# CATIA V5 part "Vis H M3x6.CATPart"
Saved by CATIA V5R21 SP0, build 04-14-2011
Part number: Vis H M3x6
Material "Acier": density 7860 kg/m3, Young's modulus 2e+11 Pa, Poisson ratio 0.266, thermal expansion 1.17e-05 1/K
Bounding box of the stored display mesh (mm): x -2.5 to 2.5, y -2.887 to 2.887, z 0 to 8
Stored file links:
  C:\Users\Olivier\Desktop\redaction CATIA (local)\CATIA\DONNEES\Exercice assemblage 1 (chassis et socle)\Assemblage chassis et socle (Product inclus)\Vis H M3x6.CATPart
  C:\Program Files\Dassault Systemes\B21\win_b64\startup\materials\French\Catalog.CATMaterial
  C:\Users\Olivier\Desktop\redaction CATIA (local)\CATIA\DONNEES\Exercice assemblage 1 (chassis et socle)\Assemblage chassis et socle (Product inclus)\CATIA_EnvironmentMap_Satin_512x512.jpg
  C:\Users\Olivier\Desktop\redaction CATIA (local)\pompe à moteur de ventilation refait\Pompe_a_moteur_de_ventilation.CATProduct
  C:\Users\Olivier\Desktop\redaction CATIA (local)\pompe à moteur de ventilation refait\Ecrou a collerette M5.CATPart
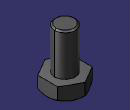
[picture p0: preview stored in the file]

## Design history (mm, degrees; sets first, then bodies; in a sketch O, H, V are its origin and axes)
Body1 (main body), material "Acier"
  Sketch1 on xy-plane, origin (0, 0, 0), H (1, 0, 0), V (0, 1, 0)
    circle A1 centre (0, 0) radius 1.5
    point P1 (2.5, -1.4434)
    point P2 (2.5, 1.4434)
    point P3 (0, 2.8868)
    point P4 (-2.5, 1.4434)
    point P5 (-2.5, -1.4434)
    point P6 (0, -2.8868)
    point P7 (2.5, 0)
    line L1 (2.5, -1.4434) -> (2.5, 1.4434)
    line L2 (2.5, 1.4434) -> (0, 2.8868)
    line L3 (0, 2.8868) -> (-2.5, 1.4434)
    line L4 (-2.5, 1.4434) -> (-2.5, -1.4434)
    line L5 (-2.5, -1.4434) -> (0, -2.8868)
    line L6 (0, -2.8868) -> (2.5, -1.4434)
    construction line L7 (0, 0) -> (2.5, 0)
    construction circle A2 centre (0, 0) radius 2.8868
    construction arc A3 centre (-2.5, -1.4434) radius 2.8868 from (-2.5, 1.4434) to (0, -2.8868) cw
    construction arc A4 centre (2.5, 1.4434) radius 2.8868 from (0, 2.8868) to (2.5, -1.4434) ccw
    distance L1 L4 = 5
    horizontal: L7 H
    coincidence: A2 P1, A2 P2, A2 P3, A2 P4, A2 P5, A2 P6, A3 O, A4 O
    midpoint: P7 L1
  MultiPad1: profile Sketch1, domains (length 2; length 8)
  Sketch2 on yz-plane, origin (0, 0, 0), H (0, 1, 0), V (0, 0, 1)
    line L1 (2.509, 0) -> (2.9319, 0.3605)
    point P1 (2.509, 0)
    line L2 (2.9319, 0.3605) -> (2.9319, 0)
    point P3 (2.9319, 0)
    line L3 (2.9319, 0) -> (2.509, 0)
    coincidence: P1 H, P3 H
    vertical: L2 V
    horizontal: L3 H
  Groove1: profile Sketch2, axis Sketch2.V, angle 360
  Chamfer1: length 0.2, angle 45, on face of MultiPad1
